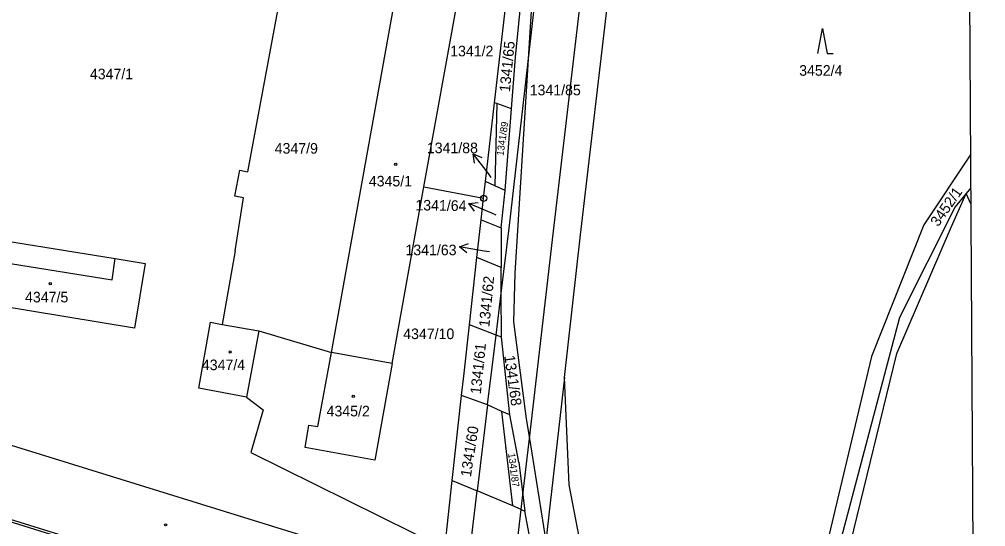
# Model space of a CAD drawing. Extents: x -735036 to -734743, y -1144813 to -1144181.
# Drawn here: x -734898.4 to -734743, y -1144480 to -1144398.5 of the extents above; entities that cross this region are included whole.
import ezdxf

# ---------------------------------------------------------------- set-up
doc = ezdxf.new("R2010")
doc.units = 0
for name, color, linetype in [('000_rozpiska', 7, 'Continuous'), ('BPEJ', 7, 'Continuous'), ('Katastr_HRANICE DRÁHY', 7, 'Continuous'), ('Katastr_Hranice parcel', 7, 'Continuous'), ('Katastr_Parcelní čísla', 7, 'Continuous'), ('Katastr_Slučkované čáry', 7, 'Continuous'), ('Katastr_Značky kultur', 7, 'Continuous')]:
    doc.layers.add(name, color=color, linetype=linetype)

msp = doc.modelspace()

# ---------------------------------------------------------------- linework, layer by layer
at = {"layer": '000_rozpiska'}
msp.add_line((-734743.05, -1144810.64), (-734746.94, -1144180.65), dxfattribs=at)
at = {"layer": 'BPEJ'}
msp.add_lwpolyline([(-734745.43, -1144425.57), (-734746.2, -1144426.51), (-734747.96, -1144428.65), (-734756.9, -1144446.43), (-734767.25, -1144485.5)], dxfattribs=at)
at = {"layer": 'Defpoints'}
msp.add_line((-734743.05, -1144810.64), (-734745.64, -1144390.65), dxfattribs=at)
at = {"layer": 'Katastr_HRANICE DRÁHY'}
for p, q in [((-734863.76, -1144426.93), (-734862.99, -1144422.76)), ((-734862.99, -1144422.76), (-734861.74, -1144422.99)), ((-734862.39, -1144427.18), (-734863.76, -1144426.93)), ((-734863.72, -1144435.68), (-734862.39, -1144427.18)), ((-734861.92, -1144459.22), (-734859.22, -1144461.28)), ((-734859.22, -1144461.28), (-734861.21, -1144468.1)), ((-734861.21, -1144468.1), (-734830.02, -1144483.57))]:
    msp.add_line(p, q, dxfattribs=at)
for points in [[(-734856.46, -1144394.74), (-734861.74, -1144422.99)], [(-734863.72, -1144435.68), (-734865.79, -1144447.52)], [(-734869.58, -1144457.79), (-734867.66, -1144447.19)], [(-734867.66, -1144447.19), (-734865.79, -1144447.52)], [(-734861.92, -1144459.22), (-734869.58, -1144457.79)]]:
    msp.add_lwpolyline(points, dxfattribs=at)
at = {"layer": 'Katastr_Hranice parcel'}
for p, q in [((-734833.36, -1144425.43), (-734827.31, -1144391.78)), ((-734822.01, -1144411.9), (-734820.19, -1144396.14)), ((-734823.77, -1144427.26), (-734823.46, -1144424.57)), ((-734830.02, -1144483.57), (-734828.81, -1144472.64))]:
    msp.add_line(p, q, dxfattribs=at)
for points in [[(-734848.25, -1144452.02), (-734837.31, -1144391.22)], [(-734815.76, -1144391.08), (-734816.67, -1144405.73)], [(-734808.21, -1144433.11), (-734803.24, -1144391.01)], [(-734818.66, -1144404.58), (-734817.92, -1144397.01)], [(-734819.31, -1144412.88), (-734818.66, -1144404.58)], [(-734816.67, -1144405.73), (-734818.75, -1144439.28)], [(-734823.46, -1144424.57), (-734822.01, -1144411.9)], [(-734821.62, -1144412.04), (-734822.01, -1144411.9)], [(-734821.62, -1144412.04), (-734821.97, -1144425.24)], [(-734819.31, -1144412.88), (-734821.62, -1144412.04)], [(-734820.32, -1144425.99), (-734819.31, -1144412.88)], [(-734745.46, -1144420.16), (-734752.99, -1144431.55)], [(-734838.46, -1144453.82), (-734833.36, -1144425.43)], [(-734833.36, -1144425.43), (-734823.77, -1144427.26)], [(-734821.97, -1144425.24), (-734823.46, -1144424.57)], [(-734820.32, -1144425.99), (-734821.97, -1144425.24)], [(-734820.97, -1144432.03), (-734820.32, -1144425.99)], [(-734748.56, -1144431.79), (-734746.2, -1144426.51)], [(-734746.2, -1144426.51), (-734747.96, -1144428.65)], [(-734745.43, -1144425.57), (-734746.2, -1144426.51)], [(-734745.41, -1144428.13), (-734746.2, -1144426.51)], [(-734824.17, -1144430.72), (-734823.77, -1144427.26)], [(-734747.96, -1144428.65), (-734756.9, -1144446.43)], [(-734824.84, -1144436.79), (-734824.17, -1144430.72)], [(-734824.17, -1144430.72), (-734820.97, -1144432.03)], [(-734752.99, -1144431.55), (-734761.43, -1144452.7)], [(-734820.97, -1144432.03), (-734820.97, -1144438.4)], [(-734810.79, -1144456.08), (-734808.21, -1144433.11)], [(-734757.32, -1144452.22), (-734748.56, -1144431.79)], [(-734900.62, -1144434.11), (-734883, -1144436.95)], [(-734883, -1144436.95), (-734878.19, -1144437.75)], [(-734878.19, -1144437.75), (-734879.9, -1144448.12)], [(-734826.04, -1144447.62), (-734824.84, -1144436.79)], [(-734820.97, -1144438.4), (-734824.84, -1144436.79)], [(-734820.94, -1144442.53), (-734820.97, -1144438.4)], [(-734818.75, -1144439.28), (-734818.94, -1144447.13)], [(-734820.88, -1144449.56), (-734820.94, -1144442.53)], [(-734879.9, -1144448.12), (-734907.55, -1144443.6)], [(-734818.94, -1144447.13), (-734816.91, -1144462.68)], [(-734756.9, -1144446.43), (-734767.25, -1144485.5)], [(-734865.79, -1144447.52), (-734859.89, -1144448.56)], [(-734859.89, -1144448.56), (-734861.92, -1144459.22)], [(-734859.89, -1144448.56), (-734848.25, -1144452.02)], [(-734826.96, -1144455.87), (-734826.04, -1144447.62)], [(-734821.75, -1144449.23), (-734826.04, -1144447.62)], [(-734820.88, -1144449.56), (-734821.75, -1144449.23)], [(-734819.57, -1144462.07), (-734820.88, -1144449.56)], [(-734850.4, -1144463.96), (-734848.25, -1144452.02)], [(-734838.46, -1144453.82), (-734848.25, -1144452.02)], [(-734761.43, -1144452.7), (-734769.6, -1144487.14)], [(-734764.76, -1144482.73), (-734757.32, -1144452.22)], [(-734838.46, -1144453.82), (-734841.25, -1144469.34)], [(-734827.3, -1144458.97), (-734826.96, -1144455.87)], [(-734810.79, -1144456.08), (-734813.74, -1144482.35)], [(-734810.02, -1144473.32), (-734810.79, -1144456.08)], [(-734828.81, -1144472.64), (-734827.3, -1144458.97)], [(-734823.12, -1144460.47), (-734827.3, -1144458.97)], [(-734820.84, -1144461.5), (-734823.12, -1144460.47)], [(-734819.57, -1144462.07), (-734820.84, -1144461.5)], [(-734819.07, -1144476.7), (-734820.84, -1144461.5)], [(-734818.11, -1144469.69), (-734819.57, -1144462.07)], [(-734816.91, -1144462.68), (-734816.4, -1144465.87)], [(-734852.45, -1144467.31), (-734851.86, -1144463.72)], [(-734851.86, -1144463.72), (-734850.4, -1144463.96)], [(-734816.4, -1144465.87), (-734813.74, -1144482.35)], [(-734902.72, -1144466.02), (-734842.51, -1144484.69)], [(-734841.25, -1144469.34), (-734852.45, -1144467.31)], [(-734818.11, -1144469.69), (-734817.45, -1144474.93)], [(-734828.81, -1144472.64), (-734824.8, -1144474.27)], [(-734800.88, -1144520.61), (-734810.02, -1144473.32)], [(-734917.71, -1144473.71), (-734876.91, -1144486.38)], [(-734819.07, -1144476.7), (-734824.8, -1144474.27)], [(-734817.45, -1144474.93), (-734817.12, -1144477.54)], [(-734817.72, -1144477.28), (-734819.07, -1144476.7)], [(-734850.95, -1144494.07), (-734906.11, -1144476.96)], [(-734817.72, -1144477.28), (-734817.12, -1144477.54)], [(-734814.66, -1144490.59), (-734817.12, -1144477.54)]]:
    msp.add_lwpolyline(points, dxfattribs=at)
at = {"layer": 'Katastr_Parcelní čísla'}
for p, q in [((-734825.26, -1144421.61), (-734825.46, -1144420.12)), ((-734822.54, -1144423.89), (-734823.01, -1144423.28)), ((-734825.21, -1144429.31), (-734826.12, -1144428.11)), ((-734821.74, -1144429.95), (-734822.43, -1144429.66)), ((-734826.48, -1144436), (-734827.63, -1144435.04)), ((-734822.84, -1144435.88), (-734823.69, -1144435.73))]:
    msp.add_line(p, q, dxfattribs=at)
for points in [[(-734823.01, -1144423.28), (-734825.46, -1144420.12), (-734824.07, -1144420.69)], [(-734822.43, -1144429.66), (-734826.12, -1144428.11), (-734824.63, -1144427.92)], [(-734823.69, -1144435.73), (-734827.63, -1144435.04), (-734826.22, -1144434.52)]]:
    msp.add_lwpolyline(points, dxfattribs=at)
at = {"layer": 'Katastr_Slučkované čáry'}
for points in [[(-734816.67, -1144405.73), (-734815.01, -1144391.08)], [(-734812.53, -1144432.52), (-734807.63, -1144391.03)], [(-734819.61, -1144431.61), (-734816.67, -1144405.73)], [(-734820.94, -1144442.53), (-734819.61, -1144431.61)], [(-734816.4, -1144465.87), (-734812.53, -1144432.52)], [(-734901.18, -1144437.52), (-734883.5, -1144440.36)], [(-734883.5, -1144440.36), (-734883, -1144436.95)], [(-734821.75, -1144449.23), (-734820.94, -1144442.53)], [(-734823.12, -1144460.47), (-734821.75, -1144449.23)], [(-734823.12, -1144460.47), (-734824.8, -1144474.27)], [(-734817.45, -1144474.93), (-734816.4, -1144465.87)], [(-734825.84, -1144482.82), (-734824.8, -1144474.27)], [(-734817.72, -1144477.28), (-734817.45, -1144474.93)], [(-734819.59, -1144493.44), (-734817.72, -1144477.28)]]:
    msp.add_lwpolyline(points, dxfattribs=at)
at = {"layer": 'Katastr_Značky kultur'}
msp.add_line((-734823.82, -1144427.26), (-734823.72, -1144427.26), dxfattribs=at)
msp.add_lwpolyline([(-734770.05, -1144403.98), (-734769.3, -1144399.98), (-734768.55, -1144403.98), (-734767.55, -1144403.98)], dxfattribs=at)
for centre, radius in [((-734837.9, -1144421.79), 0.175), ((-734823.77, -1144427.26), 0.499), ((-734893.45, -1144440.98), 0.175), ((-734864.51, -1144451.96), 0.175), ((-734844.73, -1144459.08), 0.175), ((-734874.9, -1144479.74), 0.175)]:
    msp.add_circle(centre, radius, dxfattribs=at)

# ---------------------------------------------------------------- texts
at = {"layer": 'Katastr_Parcelní čísla'}
for s, height, rotation, p in [('1341/65', 1.7, 84.3541, (-734819.55, -1144410.25)), ('1341/89', 1.14, 81.8181, (-734820.58, -1144420.49)), ('3452/1', 1.7, 55.1362, (-734750.68, -1144431.93)), ('1341/64', 1.7, 359.3069, (-734834.75, -1144429.2)), ('1341/62', 1.7, 84.5309, (-734822.85, -1144448.01)), ('1341/61', 1.7, 84.0626, (-734824.23, -1144458.8)), ('1341/68', 1.7, 277.952, (-734820.45, -1144452.58)), ('1341/60', 1.7, 81.2094, (-734825.82, -1144472.13)), ('1341/87', 1.14, 277.4791, (-734819.85, -1144468.28))]:
    msp.add_text(s, height=height, rotation=rotation, dxfattribs=at).set_placement(p)
for s, p in [('1341/2', (-734829.15, -1144404.44)), ('4347/1', (-734887.08, -1144408.13)), ('3452/4', (-734773.03, -1144407.56)), ('1341/85', (-734816.36, -1144410.71)), ('4347/9', (-734857.36, -1144420.08)), ('1341/88', (-734832.9, -1144420.01)), ('4345/1', (-734842.23, -1144425.35)), ('1341/63', (-734836.34, -1144436.41)), ('4347/5', (-734897.5, -1144443.99)), ('4347/10', (-734836.7, -1144449.89)), ('4347/4', (-734869.07, -1144454.88)), ('4345/2', (-734849.02, -1144462.31))]:
    msp.add_text(s, height=1.7, dxfattribs=at).set_placement(p)

doc.saveas('drawing.dxf')
